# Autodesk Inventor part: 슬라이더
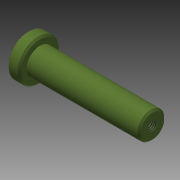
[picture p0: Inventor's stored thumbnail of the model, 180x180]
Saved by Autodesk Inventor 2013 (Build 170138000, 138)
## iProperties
Created: 2011-04
Part Number: 슬라이더
Document SubType Name: Modeling
Density: 1 g/cm^3
Material: 일반
Author: pww
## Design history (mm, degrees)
sketch "스케치1"
  geometry: L1 (-7, 0)-(63, 0); L2 (63, 0)-(63, 7.5); L3 (63, 7.5)-(0, 7.5); L4 (-7, 0)-(-7, 11.5); L5 (-7, 11.5)-(0, 11.5); L6 (0, 11.5)-(0, 7.5); 1 further point
  constraints: 12 end point, 3 perpendicular, 2 horizontal, 2 point on line, 1 parallel
  dimensions: "d1" = 70 distance of L1.start L1.end; "d19" = 15 diameter of L3 L1; "d20" = 7 distance of L4.end L5.end; "d21" = 23 diameter of L5 L1
revolve "회전1" stored, may be unused: angle "d4" = 90 deg
chamfer "모따기1" distance "d16" = 1; stored, may be unused: second distance "d17" = 2, angle "d18" = 45 deg
hole "구멍2" diameter "d24" = 4.917; stored, may be unused: countersink angle "d28" = 90 deg, drill point angle "d30" = 118 deg; dims "d22" = 10, "d23" = 10, "d25" = 10, "d26" = 4, "d27" = 2, "d29" = 13
node "솔리드1"
